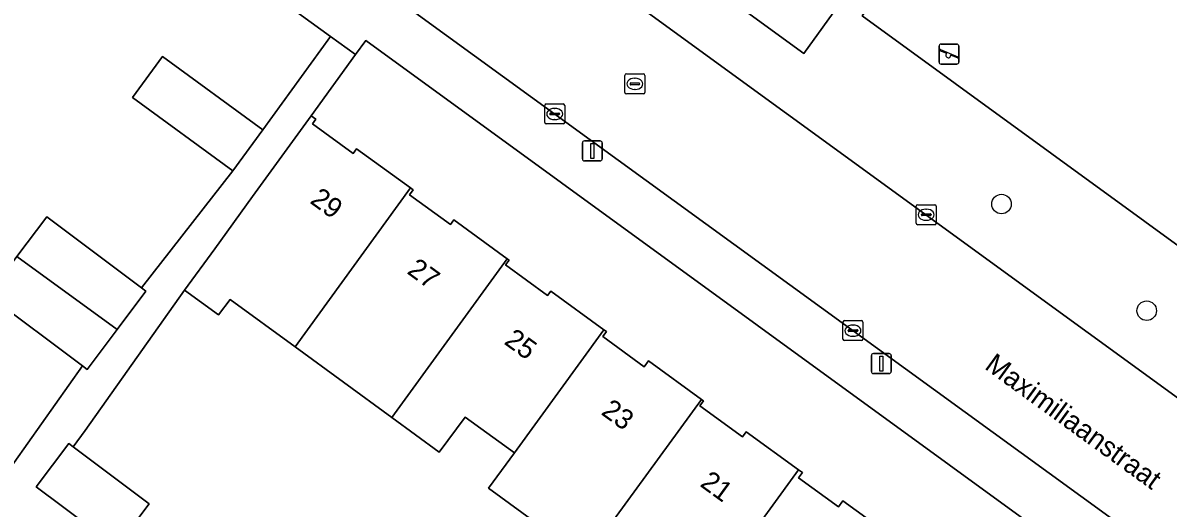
# Model space of a CAD drawing. Extents: x 159674 to 160531, y 382172 to 382904.
# Drawn here: x 160017.6 to 160074.9, y 382413.9 to 382438.2 of the extents above; entities that cross this region are included whole.
import ezdxf

# ---------------------------------------------------------------- set-up
doc = ezdxf.new("R2010")
doc.units = 0
for name, color, linetype in [('IMGEO_Boom', 7, 'Continuous'), ('IMGEO_Erf', 7, 'Continuous'), ('IMGEO_Groenvoorziening', 7, 'Continuous'), ('IMGEO_Kolk', 7, 'Continuous'), ('IMGEO_Lichtmast', 7, 'Continuous'), ('IMGEO_Openbare_ruimte_label', 7, 'Continuous'), ('IMGEO_Pand', 7, 'Continuous'), ('IMGEO_Pand_nummerreeks', 7, 'Continuous'), ('IMGEO_Rijbaan_lokaal_open', 7, 'Continuous'), ('IMGEO_Rioolput', 7, 'Continuous'), ('IMGEO_Speelvoorziening', 7, 'Continuous'), ('IMGEO_Voetpad_open', 7, 'Continuous')]:
    doc.layers.add(name, color=color, linetype=linetype)

msp = doc.modelspace()

# ---------------------------------------------------------------- linework, layer by layer
at = {"layer": 'IMGEO_Boom'}
for centre in [(160066.569, 382429.126), (160073.836, 382423.786)]:
    msp.add_circle(centre, 0.489, dxfattribs=at)
at = {"layer": 'IMGEO_Erf'}
for points in [[(160095.853, 382488.776), (160093.109, 382485.042), (160086.78, 382476.254), (160084.42, 382472.917), (160083.291, 382471.347), (160082.163, 382469.777), (160081.035, 382468.207), (160079.906, 382466.638), (160078.778, 382465.068), (160077.649, 382463.498), (160076.521, 382461.928), (160075.392, 382460.359), (160074.264, 382458.789), (160073.136, 382457.219), (160072.007, 382455.649), (160068.6, 382451.01), (160062.271, 382442.237), (160059.604, 382438.555), (160125.462, 382390.566)], [(160020.603, 382421.017), (160015.871, 382424.569), (160017.315, 382426.492), (160018.807, 382428.481), (160023.542, 382424.928), (160028.125, 382430.798), (160023.1, 382434.457), (160024.594, 382436.509), (160029.619, 382432.851), (160033.01, 382437.511), (160011.345, 382453.23)], [(160083.531, 382401.81), (160034.768, 382437.312), (160034.251, 382436.61), (160032.039, 382433.542), (160032.266, 382433.376), (160032.097, 382433.143), (160034.136, 382431.659), (160034.309, 382431.896), (160037.005, 382429.932), (160037.136, 382429.837), (160036.957, 382429.592), (160039, 382428.104), (160039.166, 382428.333), (160041.844, 382426.384), (160041.934, 382426.318), (160041.759, 382426.076), (160043.859, 382424.547), (160044.022, 382424.771), (160046.682, 382422.833), (160046.805, 382422.744), (160046.62, 382422.49), (160048.7, 382420.976), (160048.913, 382421.27), (160051.563, 382419.341), (160051.661, 382419.269), (160051.485, 382419.028), (160053.62, 382417.473), (160053.804, 382417.726), (160056.422, 382415.82), (160056.613, 382415.681), (160056.422, 382415.419), (160058.412, 382413.969), (160058.626, 382414.263), (160061.297, 382412.318)], [(160045.725, 382411.376), (160040.904, 382414.902), (160042.201, 382416.661), (160039.748, 382418.445), (160038.448, 382416.698), (160036.073, 382418.435), (160031.229, 382421.977), (160027.987, 382424.348), (160027.41, 382423.571), (160025.702, 382424.81), (160020.735, 382417.792), (160020.135, 382416.965), (160023.931, 382414.118), (160022.545, 382412.269)], [(159979.733, 382409.536), (160000, 382394.771), (160001.186, 382393.907), (160004.555, 382398.53), (160000, 382401.849), (159999.482, 382402.226), (160000, 382402.937), (160000.92, 382404.2), (160003.553, 382402.281), (160005.738, 382405.28), (160008.178, 382403.501), (160008.748, 382404.326), (160004.664, 382407.285), (160005.25, 382408.095), (160004.279, 382408.799), (160006.758, 382412.221), (160011.718, 382408.628), (160013.471, 382411.167), (160013.633, 382411.383), (160008.803, 382415.005), (160010.178, 382416.839), (160011.675, 382418.835), (160016.505, 382415.212), (160020.603, 382421.017)]]:
    msp.add_lwpolyline(points, dxfattribs=at)
at = {"layer": 'IMGEO_Groenvoorziening'}
msp.add_lwpolyline([(160054.806, 382445.584), (160052.977, 382443.048), (160051.245, 382440.646), (160056.683, 382436.674), (160058.575, 382439.306), (160060.282, 382441.681)], close=True, dxfattribs=at)
at = {"layer": 'IMGEO_Kolk'}
for p, q in [((160043.719, 382433.212), (160043.719, 382434.064)), ((160043.794, 382434.138), (160044.646, 382434.138)), ((160043.978, 382433.632), (160043.978, 382433.644)), ((160044.416, 382433.595), (160044.018, 382433.595)), ((160044.021, 382433.681), (160044.419, 382433.681)), ((160044.207, 382433.918), (160044.232, 382433.918)), ((160044.462, 382433.644), (160044.462, 382433.632)), ((160044.72, 382434.064), (160044.72, 382433.212)), ((160044.646, 382433.138), (160043.794, 382433.138)), ((160044.23, 382433.358), (160044.205, 382433.358)), ((160062.303, 382428.165), (160062.303, 382429.017)), ((160062.378, 382429.091), (160063.23, 382429.091)), ((160063.304, 382429.017), (160063.304, 382428.165)), ((160062.562, 382428.585), (160062.562, 382428.597)), ((160063, 382428.548), (160062.602, 382428.548)), ((160062.605, 382428.634), (160063.003, 382428.634)), ((160062.791, 382428.871), (160062.816, 382428.871)), ((160063.046, 382428.597), (160063.046, 382428.585)), ((160063.23, 382428.091), (160062.378, 382428.091)), ((160062.814, 382428.311), (160062.789, 382428.311)), ((160058.715, 382423.287), (160059.567, 382423.287)), ((160058.64, 382422.361), (160058.64, 382423.213)), ((160058.899, 382422.781), (160058.899, 382422.793)), ((160059.337, 382422.744), (160058.939, 382422.744)), ((160058.942, 382422.83), (160059.34, 382422.83)), ((160059.128, 382423.067), (160059.153, 382423.067)), ((160059.383, 382422.793), (160059.383, 382422.781)), ((160059.641, 382423.213), (160059.641, 382422.361)), ((160059.567, 382422.287), (160058.715, 382422.287)), ((160059.151, 382422.507), (160059.126, 382422.507))]:
    msp.add_line(p, q, dxfattribs=at)
for points in [[(160043.719, 382433.212), (160043.719, 382434.064)], [(160043.794, 382434.138), (160044.646, 382434.138)], [(160044.72, 382434.064), (160044.72, 382433.212)], [(160044.646, 382433.138), (160043.794, 382433.138)], [(160062.303, 382428.165), (160062.303, 382429.017)], [(160062.378, 382429.091), (160063.23, 382429.091)], [(160063.304, 382429.017), (160063.304, 382428.165)], [(160063.23, 382428.091), (160062.378, 382428.091)], [(160058.715, 382423.287), (160059.567, 382423.287)], [(160058.64, 382422.361), (160058.64, 382423.213)], [(160059.641, 382423.213), (160059.641, 382422.361)], [(160059.567, 382422.287), (160058.715, 382422.287)]]:
    msp.add_lwpolyline(points, dxfattribs=at)
for centre, radius, start, end in [((160043.796, 382434.062), 0.0765, 91.552, 178.448), ((160043.796, 382434.062), 0.0765, 91.552, 178.448), ((160044.018, 382433.641), 0.0403, 85.8775, 175.7526), ((160044.015, 382433.631), 0.0366, 178.938, 274.7102), ((160044.419, 382433.638), 0.043, 264.8664, 352.4533), ((160044.423, 382433.643), 0.0386, 1.7309, 96.639), ((160044.644, 382434.062), 0.0765, 1.552, 88.448), ((160044.644, 382434.062), 0.0765, 1.552, 88.448), ((160043.796, 382433.214), 0.0765, 181.552, 268.448), ((160043.796, 382433.214), 0.0765, 181.552, 268.448), ((160044.644, 382433.214), 0.0765, 271.552, 358.448), ((160044.644, 382433.214), 0.0765, 271.552, 358.448), ((160062.38, 382429.015), 0.0765, 91.552, 178.448), ((160062.38, 382429.015), 0.0765, 91.552, 178.448), ((160063.228, 382429.015), 0.0765, 1.552, 88.448), ((160063.228, 382429.015), 0.0765, 1.552, 88.448), ((160062.602, 382428.594), 0.0403, 85.8775, 175.7526), ((160062.599, 382428.584), 0.0366, 178.938, 274.7102), ((160063.003, 382428.591), 0.043, 264.8664, 352.4533), ((160063.007, 382428.596), 0.0386, 1.7309, 96.639), ((160062.38, 382428.167), 0.0765, 181.552, 268.448), ((160062.38, 382428.167), 0.0765, 181.552, 268.448), ((160063.228, 382428.167), 0.0765, 271.552, 358.448), ((160063.228, 382428.167), 0.0765, 271.552, 358.448), ((160058.717, 382423.211), 0.0765, 91.552, 178.448), ((160058.717, 382423.211), 0.0765, 91.552, 178.448), ((160059.565, 382423.211), 0.0765, 1.552, 88.448), ((160059.565, 382423.211), 0.0765, 1.552, 88.448), ((160058.939, 382422.79), 0.0403, 85.8775, 175.7526), ((160058.936, 382422.78), 0.0366, 178.938, 274.7102), ((160059.34, 382422.787), 0.043, 264.8664, 352.4533), ((160059.344, 382422.792), 0.0386, 1.7309, 96.639), ((160058.717, 382422.363), 0.0765, 181.552, 268.448), ((160058.717, 382422.363), 0.0765, 181.552, 268.448), ((160059.565, 382422.363), 0.0765, 271.552, 358.448), ((160059.565, 382422.363), 0.0765, 271.552, 358.448)]:
    msp.add_arc(centre, radius, start, end, dxfattribs=at)
for centre, major_axis, ratio, start_param, end_param in [((160044.206, 382433.638), (-0.387, 0.002), 0.722429, 4.712389, 7.853982), ((160044.231, 382433.638), (-0.39, 0.002), 0.717154, 1.570796, 4.712389), ((160062.79, 382428.591), (-0.387, 0.002), 0.722429, 4.712389, 7.853982), ((160062.815, 382428.591), (-0.39, 0.002), 0.717154, 1.570796, 4.712389), ((160059.127, 382422.787), (-0.387, 0.002), 0.722429, 4.712389, 7.853982), ((160059.152, 382422.787), (-0.39, 0.002), 0.717154, 1.570796, 4.712389)]:
    msp.add_ellipse(centre, major_axis=major_axis, ratio=ratio, start_param=start_param, end_param=end_param, dxfattribs=at)
at = {"layer": 'IMGEO_Lichtmast'}
for p, q in [((160045.605, 382431.388), (160045.605, 382432.188)), ((160045.605, 382432.188), (160045.605, 382431.388)), ((160045.705, 382432.288), (160046.495, 382432.288)), ((160046.495, 382432.288), (160045.705, 382432.288)), ((160046.595, 382432.188), (160046.595, 382431.388)), ((160046.595, 382431.388), (160046.595, 382432.188)), ((160046.495, 382431.288), (160045.705, 382431.288)), ((160045.705, 382431.288), (160046.495, 382431.288)), ((160060.163, 382421.64), (160060.953, 382421.64)), ((160060.953, 382421.64), (160060.163, 382421.64)), ((160060.063, 382420.74), (160060.063, 382421.54)), ((160060.063, 382421.54), (160060.063, 382420.74)), ((160061.053, 382421.54), (160061.053, 382420.74)), ((160061.053, 382420.74), (160061.053, 382421.54)), ((160060.953, 382420.64), (160060.163, 382420.64)), ((160060.163, 382420.64), (160060.953, 382420.64))]:
    msp.add_line(p, q, dxfattribs=at)
for points in [[(160046.025, 382432.163), (160046.175, 382432.163), (160046.175, 382431.413), (160046.025, 382431.413), (160046.025, 382432.163)], [(160060.483, 382421.515), (160060.633, 382421.515), (160060.633, 382420.765), (160060.483, 382420.765), (160060.483, 382421.515)]]:
    msp.add_lwpolyline(points, dxfattribs=at)
for centre, start, end in [((160045.705, 382432.188), 90, 180), ((160045.705, 382432.188), 90, 180), ((160046.495, 382432.188), 0, 90), ((160046.495, 382432.188), 360, 90), ((160045.705, 382431.388), 180, 270), ((160045.705, 382431.388), 180, 270), ((160046.495, 382431.388), 270, 0), ((160046.495, 382431.388), 270, 0), ((160060.163, 382421.54), 90, 180), ((160060.163, 382421.54), 90, 180), ((160060.953, 382421.54), 0, 90), ((160060.953, 382421.54), 360, 90), ((160060.163, 382420.74), 180, 270), ((160060.163, 382420.74), 180, 270), ((160060.953, 382420.74), 270, 0), ((160060.953, 382420.74), 270, 0)]:
    msp.add_arc(centre, 0.1, start, end, dxfattribs=at)
at = {"layer": 'IMGEO_Pand'}
for points in [[(160028.125, 382430.798), (160029.619, 382432.851), (160024.594, 382436.509), (160023.1, 382434.457)], [(160031.229, 382421.977), (160037.005, 382429.932), (160034.309, 382431.896), (160034.136, 382431.659), (160032.097, 382433.143), (160032.266, 382433.376), (160032.039, 382433.542), (160029.096, 382429.5), (160027.215, 382426.884), (160025.702, 382424.81), (160027.41, 382423.571), (160027.987, 382424.348)], [(160031.229, 382421.977), (160036.073, 382418.435), (160041.844, 382426.384), (160039.166, 382428.333), (160039, 382428.104), (160036.957, 382429.592), (160037.136, 382429.837), (160037.005, 382429.932)], [(160017.315, 382426.492), (160022.338, 382422.851), (160023.768, 382424.758), (160023.542, 382424.928), (160018.807, 382428.481)], [(160017.315, 382426.492), (160015.871, 382424.569), (160020.603, 382421.017), (160020.832, 382420.845), (160022.338, 382422.851)], [(160046.682, 382422.833), (160044.022, 382424.771), (160043.859, 382424.547), (160041.759, 382426.076), (160041.934, 382426.318), (160041.844, 382426.384), (160036.073, 382418.435), (160038.448, 382416.698), (160039.748, 382418.445), (160042.201, 382416.661)], [(160051.563, 382419.341), (160048.913, 382421.27), (160048.7, 382420.976), (160046.62, 382422.49), (160046.805, 382422.744), (160046.682, 382422.833), (160042.201, 382416.661), (160040.904, 382414.902), (160045.725, 382411.376), (160045.904, 382411.621), (160046.719, 382412.671)], [(160056.422, 382415.82), (160053.804, 382417.726), (160053.62, 382417.473), (160051.485, 382419.028), (160051.661, 382419.269), (160051.563, 382419.341), (160046.719, 382412.671), (160048.156, 382411.625), (160048.483, 382412.073), (160051.892, 382409.591)], [(160020.135, 382416.965), (160019.913, 382417.132), (160018.288, 382414.965), (160022.306, 382411.951), (160022.545, 382412.269), (160023.931, 382414.118)], [(160061.297, 382412.318), (160058.626, 382414.263), (160058.412, 382413.969), (160056.422, 382415.419), (160056.613, 382415.681), (160056.422, 382415.82), (160051.892, 382409.591), (160051.57, 382409.148), (160049.32, 382406.038), (160054.119, 382402.544), (160055.378, 382404.167)]]:
    msp.add_lwpolyline(points, close=True, dxfattribs=at)
at = {"layer": 'IMGEO_Rijbaan_lokaal_open'}
for points in [[(160123.455, 382384.426), (160018.366, 382460.946)], [(160014.616, 382455.167), (160030.935, 382443.3), (160034.415, 382440.769), (160099.29, 382393.592), (160102.339, 382391.375), (160119.102, 382379.184)]]:
    msp.add_lwpolyline(points, dxfattribs=at)
at = {"layer": 'IMGEO_Rioolput'}
for p, q in [((160047.729, 382434.721), (160047.729, 382435.573)), ((160047.804, 382435.647), (160048.656, 382435.647)), ((160048.217, 382435.427), (160048.242, 382435.427)), ((160048.73, 382435.573), (160048.73, 382434.721)), ((160047.988, 382435.141), (160047.988, 382435.153)), ((160048.426, 382435.104), (160048.028, 382435.104)), ((160048.031, 382435.19), (160048.429, 382435.19)), ((160048.24, 382434.867), (160048.215, 382434.867)), ((160048.472, 382435.153), (160048.472, 382435.141)), ((160048.656, 382434.647), (160047.804, 382434.647))]:
    msp.add_line(p, q, dxfattribs=at)
for points in [[(160047.729, 382434.721), (160047.729, 382435.573)], [(160047.804, 382435.647), (160048.656, 382435.647)], [(160048.73, 382435.573), (160048.73, 382434.721)], [(160048.656, 382434.647), (160047.804, 382434.647)]]:
    msp.add_lwpolyline(points, dxfattribs=at)
for centre, radius, start, end in [((160047.806, 382435.571), 0.0765, 91.552, 178.448), ((160047.806, 382435.571), 0.0765, 91.552, 178.448), ((160048.654, 382435.571), 0.0765, 1.552, 88.448), ((160048.654, 382435.571), 0.0765, 1.552, 88.448), ((160048.028, 382435.15), 0.0403, 85.8775, 175.7526), ((160048.025, 382435.14), 0.0366, 178.938, 274.7102), ((160048.429, 382435.147), 0.043, 264.8664, 352.4533), ((160048.433, 382435.152), 0.0386, 1.7309, 96.639), ((160047.806, 382434.723), 0.0765, 181.552, 268.448), ((160047.806, 382434.723), 0.0765, 181.552, 268.448), ((160048.654, 382434.723), 0.0765, 271.552, 358.448), ((160048.654, 382434.723), 0.0765, 271.552, 358.448)]:
    msp.add_arc(centre, radius, start, end, dxfattribs=at)
for centre, major_axis, ratio, start_param, end_param in [((160048.216, 382435.147), (-0.387, 0.002), 0.722429, 4.712389, 7.853982), ((160048.241, 382435.147), (-0.39, 0.002), 0.717154, 1.570796, 4.712389)]:
    msp.add_ellipse(centre, major_axis=major_axis, ratio=ratio, start_param=start_param, end_param=end_param, dxfattribs=at)
at = {"layer": 'IMGEO_Speelvoorziening'}
for p, q in [((160063.446, 382436.234), (160063.446, 382437.034)), ((160063.446, 382437.034), (160063.446, 382436.234)), ((160063.546, 382437.134), (160064.336, 382437.134)), ((160064.336, 382437.134), (160063.546, 382437.134)), ((160064.436, 382437.034), (160064.436, 382436.234)), ((160064.436, 382436.234), (160064.436, 382437.034)), ((160063.829, 382436.662), (160063.49, 382436.799)), ((160063.515, 382436.859), (160064.391, 382436.506)), ((160064.367, 382436.446), (160064.027, 382436.583)), ((160064.336, 382436.134), (160063.546, 382436.134)), ((160063.546, 382436.134), (160064.336, 382436.134))]:
    msp.add_line(p, q, dxfattribs=at)
for centre, radius, start, end in [((160063.546, 382437.034), 0.1, 90, 180), ((160063.546, 382437.034), 0.1, 90, 180), ((160064.336, 382437.034), 0.1, 0, 90), ((160064.336, 382437.034), 0.1, 360, 90), ((160063.503, 382436.829), 0.0327, 68.078, 248.078), ((160063.908, 382436.572), 0.12, 130.9928, 5.1632), ((160064.379, 382436.476), 0.0327, 248.078, 68.078), ((160063.546, 382436.234), 0.1, 180, 270), ((160063.546, 382436.234), 0.1, 180, 270), ((160064.336, 382436.234), 0.1, 270, 0), ((160064.336, 382436.234), 0.1, 270, 0)]:
    msp.add_arc(centre, radius, start, end, dxfattribs=at)
at = {"layer": 'IMGEO_Voetpad_open'}
for points in [[(160018.366, 382460.946), (160123.455, 382384.426), (160127.601, 382390.967)], [(160011.345, 382453.23), (160033.01, 382437.511), (160034.251, 382436.61), (160034.768, 382437.312), (160083.531, 382401.81), (160085.455, 382400.41), (160110.564, 382382.129), (160106.732, 382376.818), (160104.611, 382373.905), (160105.953, 382372.892), (160111.288, 382369.019), (160119.102, 382379.184), (160102.339, 382391.375), (160102.045, 382390.971), (160098.996, 382393.188), (160099.29, 382393.592), (160034.415, 382440.769)], [(160125.462, 382390.566), (160059.604, 382438.555), (160062.271, 382442.237)], [(160022.306, 382411.951), (160018.288, 382414.965), (160019.913, 382417.132), (160020.135, 382416.965), (160020.735, 382417.792), (160025.702, 382424.81), (160027.215, 382426.884), (160029.096, 382429.5), (160032.039, 382433.542), (160034.251, 382436.61), (160033.01, 382437.511), (160029.619, 382432.851), (160028.125, 382430.798), (160023.542, 382424.928), (160023.768, 382424.758), (160022.338, 382422.851), (160020.832, 382420.845), (160020.603, 382421.017), (160016.505, 382415.212)]]:
    msp.add_lwpolyline(points, dxfattribs=at)
msp.add_lwpolyline([(160058.575, 382439.306), (160056.683, 382436.674), (160051.245, 382440.646), (160052.977, 382443.048), (160054.806, 382445.584), (160060.282, 382441.681)], close=True, dxfattribs=at)

# ---------------------------------------------------------------- texts
at = {"layer": 'IMGEO_Openbare_ruimte_label'}
msp.add_text('Maximiliaanstraat', height=1, rotation=323.9895, dxfattribs=at).set_placement((160065.676, 382420.908))
at = {"layer": 'IMGEO_Pand_nummerreeks'}
for s, rotation, p in [('29', 323.9907, (160031.928, 382429.211)), ('27', 323.9907, (160036.783, 382425.682)), ('25', 323.9907, (160041.639, 382422.153)), ('23', 323.9896, (160046.494, 382418.624)), ('21', 323.9896, (160051.44, 382415.029))]:
    msp.add_text(s, height=1, rotation=rotation, dxfattribs=at).set_placement(p)

doc.saveas('drawing.dxf')
